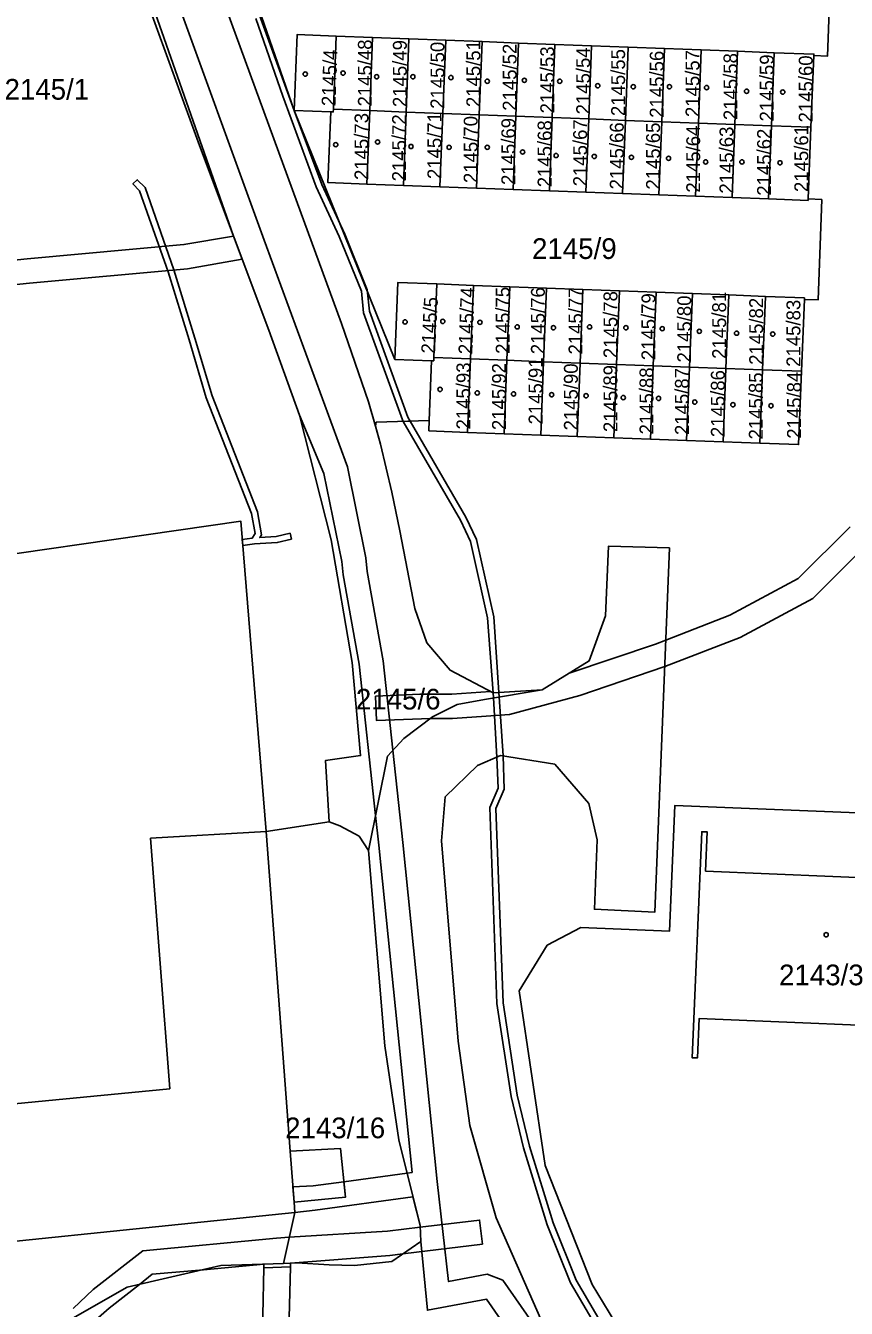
# Model space of a CAD drawing. Extents: x -756746 to -753363, y -1166406 to -1161727.
# Drawn here: x -756523.9 to -756456.5, y -1164106.4 to -1164001 of the extents above; entities that cross this region are included whole.
import ezdxf

# ---------------------------------------------------------------- set-up
doc = ezdxf.new("R2010")
doc.units = 0
for name, color, linetype in [('Hranice parcel', 7, 'Continuous'), ('Parcelní čísla', 7, 'Continuous'), ('Vnitřní kresba', 7, 'Continuous'), ('Věcná břemena k části', 7, 'Continuous'), ('Značky budov', 7, 'Continuous')]:
    doc.layers.add(name, color=color, linetype=linetype)

msp = doc.modelspace()

# ---------------------------------------------------------------- linework, layer by layer
at = {"layer": 'Hranice parcel'}
for p, q in [((-756514.38, -1163973.31), (-756501.8, -1164008)), ((-756498.59, -1164007.9), (-756498.37, -1164001.89)), ((-756498.37, -1164001.89), (-756495.37, -1164002)), ((-756495.6, -1164008.01), (-756495.37, -1164002)), ((-756495.37, -1164002), (-756492.38, -1164002.12)), ((-756492.6, -1164008.13), (-756492.38, -1164002.12)), ((-756492.38, -1164002.12), (-756489.36, -1164002.23)), ((-756489.6, -1164008.24), (-756489.36, -1164002.23)), ((-756489.36, -1164002.23), (-756486.37, -1164002.34)), ((-756486.6, -1164008.35), (-756486.37, -1164002.34)), ((-756486.37, -1164002.34), (-756483.39, -1164002.46)), ((-756483.61, -1164008.47), (-756483.39, -1164002.46)), ((-756483.39, -1164002.46), (-756480.39, -1164002.57)), ((-756480.61, -1164008.58), (-756480.39, -1164002.57)), ((-756480.39, -1164002.57), (-756477.38, -1164002.68)), ((-756477.61, -1164008.69), (-756477.38, -1164002.68)), ((-756477.38, -1164002.68), (-756474.37, -1164002.8)), ((-756474.6, -1164008.81), (-756474.37, -1164002.8)), ((-756474.37, -1164002.8), (-756471.38, -1164002.91)), ((-756471.62, -1164008.92), (-756471.38, -1164002.91)), ((-756471.38, -1164002.91), (-756468.37, -1164003.02)), ((-756468.6, -1164009.03), (-756468.37, -1164003.02)), ((-756468.37, -1164003.02), (-756465.38, -1164003.13)), ((-756465.61, -1164009.14), (-756465.38, -1164003.13)), ((-756465.38, -1164003.13), (-756462.38, -1164003.25)), ((-756462.61, -1164009.26), (-756462.38, -1164003.25)), ((-756459.36, -1164009.38), (-756459.13, -1164003.49)), ((-756501.8, -1164008), (-756498.79, -1164008.11)), ((-756501.8, -1164008), (-756493.54, -1164028.45)), ((-756498.59, -1164007.9), (-756495.6, -1164008.01)), ((-756495.6, -1164008.01), (-756495.83, -1164014.05)), ((-756495.6, -1164008.01), (-756492.6, -1164008.13)), ((-756492.6, -1164008.13), (-756492.83, -1164014.16)), ((-756492.6, -1164008.13), (-756489.6, -1164008.24)), ((-756489.6, -1164008.24), (-756489.84, -1164014.27)), ((-756489.6, -1164008.24), (-756486.6, -1164008.35)), ((-756486.6, -1164008.35), (-756486.83, -1164014.38)), ((-756486.6, -1164008.35), (-756483.61, -1164008.47)), ((-756483.61, -1164008.47), (-756483.83, -1164014.49)), ((-756483.61, -1164008.47), (-756480.61, -1164008.58)), ((-756480.61, -1164008.58), (-756480.84, -1164014.6)), ((-756480.61, -1164008.58), (-756477.61, -1164008.69)), ((-756477.61, -1164008.69), (-756477.85, -1164014.71)), ((-756477.61, -1164008.69), (-756474.6, -1164008.81)), ((-756474.6, -1164008.81), (-756474.83, -1164014.83)), ((-756474.6, -1164008.81), (-756471.62, -1164008.92)), ((-756471.62, -1164008.92), (-756471.86, -1164014.94)), ((-756471.62, -1164008.92), (-756468.6, -1164009.03)), ((-756468.6, -1164009.03), (-756468.84, -1164015.05)), ((-756468.6, -1164009.03), (-756465.61, -1164009.14)), ((-756465.61, -1164009.14), (-756465.84, -1164015.16)), ((-756465.61, -1164009.14), (-756462.61, -1164009.26)), ((-756462.61, -1164009.26), (-756462.84, -1164015.27)), ((-756462.61, -1164009.26), (-756459.36, -1164009.38)), ((-756459.59, -1164015.27), (-756459.36, -1164009.38)), ((-756492.83, -1164014.16), (-756495.83, -1164014.05)), ((-756489.84, -1164014.27), (-756492.83, -1164014.16)), ((-756486.83, -1164014.38), (-756489.84, -1164014.27)), ((-756483.83, -1164014.49), (-756486.83, -1164014.38)), ((-756480.84, -1164014.6), (-756483.83, -1164014.49)), ((-756477.85, -1164014.71), (-756480.84, -1164014.6)), ((-756474.83, -1164014.83), (-756477.85, -1164014.71)), ((-756471.86, -1164014.94), (-756474.83, -1164014.83)), ((-756468.84, -1164015.05), (-756471.86, -1164014.94)), ((-756465.84, -1164015.16), (-756468.84, -1164015.05)), ((-756462.84, -1164015.27), (-756465.84, -1164015.16)), ((-756490.33, -1164028.3), (-756490.08, -1164022.25)), ((-756490.08, -1164022.25), (-756487.07, -1164022.37)), ((-756487.32, -1164028.41), (-756487.07, -1164022.37)), ((-756487.07, -1164022.37), (-756484.09, -1164022.48)), ((-756484.33, -1164028.52), (-756484.09, -1164022.48)), ((-756484.09, -1164022.48), (-756481.09, -1164022.59)), ((-756481.33, -1164028.64), (-756481.09, -1164022.59)), ((-756481.09, -1164022.59), (-756478.09, -1164022.71)), ((-756478.32, -1164028.75), (-756478.09, -1164022.71)), ((-756478.09, -1164022.71), (-756475.08, -1164022.82)), ((-756475.32, -1164028.86), (-756475.08, -1164022.82)), ((-756475.08, -1164022.82), (-756472.07, -1164022.94)), ((-756472.31, -1164028.97), (-756472.07, -1164022.94)), ((-756472.07, -1164022.94), (-756469.09, -1164023.05)), ((-756469.33, -1164029.09), (-756469.09, -1164023.05)), ((-756469.09, -1164023.05), (-756466.1, -1164023.16)), ((-756466.34, -1164029.2), (-756466.1, -1164023.16)), ((-756466.1, -1164023.16), (-756463.09, -1164023.28)), ((-756463.33, -1164029.31), (-756463.09, -1164023.28)), ((-756460.13, -1164029.43), (-756459.9, -1164023.52)), ((-756490.33, -1164028.3), (-756487.32, -1164028.41)), ((-756493.54, -1164028.45), (-756490.54, -1164028.56)), ((-756490.54, -1164028.56), (-756490.73, -1164033.48)), ((-756487.32, -1164028.41), (-756487.56, -1164034.45)), ((-756487.32, -1164028.41), (-756484.33, -1164028.52)), ((-756484.33, -1164028.52), (-756484.56, -1164034.56)), ((-756484.33, -1164028.52), (-756481.33, -1164028.64)), ((-756481.33, -1164028.64), (-756481.56, -1164034.67)), ((-756481.33, -1164028.64), (-756478.32, -1164028.75)), ((-756478.32, -1164028.75), (-756478.55, -1164034.78)), ((-756478.32, -1164028.75), (-756475.32, -1164028.86)), ((-756475.32, -1164028.86), (-756475.55, -1164034.89)), ((-756475.32, -1164028.86), (-756472.31, -1164028.97)), ((-756472.31, -1164028.97), (-756472.55, -1164035)), ((-756472.31, -1164028.97), (-756469.33, -1164029.09)), ((-756469.33, -1164029.09), (-756469.57, -1164035.11)), ((-756469.33, -1164029.09), (-756466.34, -1164029.2)), ((-756466.34, -1164029.2), (-756466.57, -1164035.22)), ((-756466.34, -1164029.2), (-756463.33, -1164029.31)), ((-756463.33, -1164029.31), (-756463.57, -1164035.33)), ((-756463.33, -1164029.31), (-756460.13, -1164029.43)), ((-756490.73, -1164033.48), (-756490.76, -1164034.33)), ((-756490.76, -1164034.33), (-756487.56, -1164034.45)), ((-756487.56, -1164034.45), (-756484.56, -1164034.56)), ((-756484.56, -1164034.56), (-756481.56, -1164034.67)), ((-756481.56, -1164034.67), (-756478.55, -1164034.78)), ((-756478.55, -1164034.78), (-756475.55, -1164034.89)), ((-756475.55, -1164034.89), (-756472.55, -1164035)), ((-756472.55, -1164035), (-756469.57, -1164035.11)), ((-756469.57, -1164035.11), (-756466.57, -1164035.22)), ((-756466.57, -1164035.22), (-756463.57, -1164035.33)), ((-756485.46, -1164055.85), (-756481.45, -1164055.6)), ((-756504.1, -1164067.25), (-756498.94, -1164066.46)), ((-756498.07, -1164066.78), (-756498.94, -1164066.46)), ((-756496.46, -1164067.63), (-756498.07, -1164066.78)), ((-756495.71, -1164068.81), (-756496.46, -1164067.63)), ((-756501.76, -1164098.54), (-756546.2, -1164103.15)), ((-756502.68, -1164102.74), (-756501.76, -1164098.54))]:
    msp.add_line(p, q, dxfattribs=at)
for points in [[(-756495.13, -1164033.93), (-756495.69, -1164031.95), (-756497.93, -1164025.5), (-756501.94, -1164014.53), (-756507.37, -1163999.69), (-756510.62, -1163990.83), (-756512.8, -1163984.85), (-756516.5, -1163974.77), (-756518.28, -1163969.91), (-756519.92, -1163965.45), (-756520.74, -1163963.19), (-756522.25, -1163959.35)], [(-756497.05, -1164053.35), (-756498.78, -1164043.27), (-756501.38, -1164033.04), (-756503.9, -1164026.05), (-756509.58, -1164010.87), (-756513.68, -1163999.59), (-756518.83, -1163985.73), (-756522.65, -1163975.43), (-756522.77, -1163975.11)], [(-756459.13, -1164003.49), (-756458.01, -1164003.54), (-756457.69, -1163995.31), (-756458.82, -1163995.39), (-756458.81, -1163995.27)], [(-756498.37, -1164001.89), (-756501.57, -1164001.77), (-756501.8, -1164008)], [(-756462.38, -1164003.25), (-756459.12, -1164003.37), (-756459.13, -1164003.49)], [(-756495.83, -1164014.05), (-756499.03, -1164013.93), (-756498.79, -1164008.11)], [(-756498.79, -1164008.11), (-756498.6, -1164008.12), (-756498.59, -1164007.9)], [(-756459.59, -1164015.27), (-756459.59, -1164015.39), (-756462.84, -1164015.27)], [(-756459.9, -1164023.52), (-756458.78, -1164023.56), (-756458.47, -1164015.32), (-756459.59, -1164015.27)], [(-756490.08, -1164022.25), (-756493.28, -1164022.13), (-756493.54, -1164028.45)], [(-756463.09, -1164023.28), (-756459.9, -1164023.4), (-756459.9, -1164023.52)], [(-756490.54, -1164028.56), (-756490.34, -1164028.57), (-756490.33, -1164028.3)], [(-756463.57, -1164035.33), (-756460.37, -1164035.45), (-756460.13, -1164029.43)], [(-756490.73, -1164033.48), (-756495.06, -1164033.62), (-756495.13, -1164033.93)], [(-756495.13, -1164033.93), (-756494.71, -1164035.41), (-756493.78, -1164039.37), (-756493.13, -1164042.54), (-756491.91, -1164048.92), (-756490.92, -1164051.75), (-756489, -1164053.99), (-756485.46, -1164055.85)], [(-756504.1, -1164067.25), (-756506.19, -1164041.74), (-756535.05, -1164045.9)], [(-756480.85, -1164108.87), (-756485.22, -1164098.98), (-756487.37, -1164091.4), (-756488.33, -1164084.46), (-756489.72, -1164068), (-756489.4, -1164064.41), (-756486.76, -1164061.81), (-756484.85, -1164061), (-756480.4, -1164061.7), (-756477.61, -1164064.95), (-756476.92, -1164067.93), (-756477.15, -1164073.64), (-756472.17, -1164073.87), (-756470.98, -1164043.94), (-756475.99, -1164043.8), (-756476.23, -1164049.52), (-756477.58, -1164053.23), (-756481.45, -1164055.6)], [(-756498.94, -1164066.46), (-756499.23, -1164061.41), (-756496.36, -1164061.01), (-756497.05, -1164053.35)], [(-756481.45, -1164055.6), (-756486.17, -1164056.39), (-756488.42, -1164056.81), (-756490.44, -1164057.83), (-756492.81, -1164059.6), (-756494.14, -1164061.05), (-756495.71, -1164068.81)], [(-756389.79, -1164078.86), (-756389.34, -1164068.38), (-756470.53, -1164065.1), (-756470.97, -1164075.43), (-756478.27, -1164075.14), (-756481.04, -1164076.59), (-756483.33, -1164080.35), (-756481.19, -1164094.7), (-756477.33, -1164104.46), (-756474.07, -1164109.84), (-756463.94, -1164120.98), (-756462, -1164122.91), (-756448.38, -1164117.4), (-756426.16, -1164129.05), (-756390.59, -1164133.4), (-756390.62, -1164132.03), (-756391.47, -1164122.81), (-756390.01, -1164084.62)], [(-756501.76, -1164098.54), (-756501.82, -1164097.7), (-756497.6, -1164097.3), (-756498, -1164093.3), (-756502.14, -1164093.5), (-756504.1, -1164067.25)], [(-756446.54, -1164068.74), (-756446.52, -1164068.18), (-756446.98, -1164068.16), (-756447.11, -1164071.38), (-756468.02, -1164070.5), (-756467.88, -1164067.28), (-756468.33, -1164067.26), (-756469.13, -1164085.84), (-756468.69, -1164085.85), (-756468.55, -1164082.62), (-756447.59, -1164083.48), (-756447.72, -1164086.71), (-756447.42, -1164086.72)], [(-756495.71, -1164068.81), (-756494.37, -1164084.86), (-756493.21, -1164092.58), (-756491.47, -1164099.62), (-756491.4, -1164100.93), (-756493.8, -1164102.59), (-756496.85, -1164102.91), (-756498.93, -1164102.84), (-756501.58, -1164102.7), (-756502.68, -1164102.74)], [(-756502.68, -1164102.74), (-756507.83, -1164102.92), (-756515.54, -1164104.69), (-756520.36, -1164107.44)]]:
    msp.add_lwpolyline(points, dxfattribs=at)
at = {"layer": 'Vnitřní kresba'}
for p, q in [((-756504.1, -1164067.25), (-756513.6, -1164067.79)), ((-756513.6, -1164067.79), (-756512.02, -1164088.4)), ((-756512.02, -1164088.4), (-756544.05, -1164091.46)), ((-756501.82, -1164097.7), (-756502.14, -1164093.5))]:
    msp.add_line(p, q, dxfattribs=at)
at = {"layer": 'Věcná břemena k části'}
for points in [[(-756476.26, -1164116.2), (-756484.68, -1164104.1), (-756485.95, -1164103.63), (-756489.13, -1164104.23), (-756490.05, -1164096.01), (-756492.88, -1164068.16), (-756493.7, -1164060.57), (-756494.49, -1164053.22), (-756495.81, -1164045.88), (-756495.92, -1164044.77), (-756497.43, -1164037.28), (-756504.27, -1164018.66), (-756512.09, -1163997.16)], [(-756513.97, -1163997.84), (-756506.79, -1164018.32), (-756506.08, -1164020.22), (-756503.9, -1164026.05), (-756501.38, -1164033.04), (-756499.37, -1164037.82), (-756497.9, -1164045.07), (-756497.79, -1164046.16), (-756496.47, -1164053.5), (-756495.13, -1164065.93), (-756494.86, -1164068.36), (-756492.13, -1164095.26), (-756492.53, -1164095.32), (-756497.73, -1164096.03), (-756497.6, -1164097.3), (-756501.82, -1164097.7), (-756501.76, -1164098.54), (-756500.08, -1164098.37), (-756492.05, -1164097.27), (-756491.47, -1164099.62), (-756491.4, -1164100.93), (-756490.87, -1164106.59), (-756486.02, -1164105.67), (-756477.9, -1164117.34)], [(-756504.96, -1164000.43), (-756502.73, -1164006.82), (-756499.99, -1164014.28), (-756498.12, -1164018.35), (-756496.29, -1164022.86), (-756496.11, -1164024.62), (-756492.92, -1164033.43), (-756492.85, -1164033.55), (-756492.27, -1164033.53), (-756492.46, -1164033.21), (-756495.61, -1164024.5), (-756495.81, -1164022.74), (-756497.66, -1164018.15), (-756499.53, -1164014.08), (-756501.8, -1164008), (-756504.48, -1164000.27)], [(-756475.93, -1164108.75), (-756478.64, -1164104.11), (-756480.54, -1164099.4), (-756482.48, -1164093.1), (-756483.48, -1164088.91), (-756484.65, -1164081.33), (-756485.24, -1164065.36), (-756484.55, -1164063.78), (-756484.65, -1164061.03), (-756484.98, -1164056.19), (-756485, -1164055.82), (-756485.42, -1164049.62), (-756486.84, -1164043.25), (-756487.7, -1164041.41), (-756492.27, -1164033.53), (-756492.85, -1164033.55), (-756488.14, -1164041.65), (-756487.32, -1164043.41), (-756485.92, -1164049.7), (-756485.46, -1164055.85), (-756485.44, -1164056.27), (-756485.15, -1164061.13), (-756485.05, -1164063.68), (-756485.74, -1164065.26), (-756485.15, -1164081.37), (-756483.98, -1164089.01), (-756482.96, -1164093.24), (-756481.02, -1164099.56), (-756479.1, -1164104.33), (-756476.35, -1164109.03)], [(-756456.13, -1164042.21), (-756460.4, -1164046.47), (-756466.02, -1164049.48), (-756471.28, -1164051.52), (-756472.13, -1164051.85), (-756479.21, -1164054.23), (-756481.45, -1164055.6), (-756485.46, -1164055.85), (-756485.67, -1164055.74), (-756488.87, -1164055.95), (-756491.48, -1164055.97), (-756495.12, -1164056.13), (-756495.04, -1164058.13), (-756490.62, -1164057.96), (-756488.79, -1164057.95), (-756486.05, -1164057.78), (-756484.13, -1164057.62), (-756478.35, -1164056.07), (-756471.37, -1164053.7), (-756465.18, -1164051.3), (-756459.2, -1164048.09), (-756454.41, -1164043.31)], [(-756486.34, -1164101.15), (-756486.58, -1164099.17), (-756491.46, -1164099.76), (-756494.15, -1164100.09), (-756502.21, -1164100.59), (-756503.26, -1164100.66), (-756514.25, -1164101.69), (-756518.31, -1164104.89), (-756519.97, -1164106.45)], [(-756502.1, -1164102.72), (-756493.95, -1164102.09), (-756492.89, -1164101.96), (-756486.34, -1164101.15)], [(-756520.91, -1164109.84), (-756517.01, -1164106.41), (-756514.52, -1164104.46), (-756513.47, -1164103.63), (-756509.27, -1164103.25), (-756504.29, -1164102.8), (-756504.3, -1164103.1), (-756502.1, -1164103.02), (-756502.1, -1164102.72)]]:
    msp.add_lwpolyline(points, dxfattribs=at)
for points in [[(-756502.03, -1164043.23), (-756502.14, -1164042.74), (-756503.28, -1164043), (-756504.63, -1164043.09), (-756504.5, -1164042.87), (-756504.83, -1164040.97), (-756508.55, -1164031.45), (-756509.96, -1164026.71), (-756511.69, -1164021.1), (-756514.06, -1164014.32), (-756514.7, -1164013.69), (-756515.05, -1164014.04), (-756514.5, -1164014.6), (-756512.17, -1164021.26), (-756510.44, -1164026.85), (-756509.03, -1164031.61), (-756505.31, -1164041.11), (-756505.02, -1164042.77), (-756505.25, -1164043.14), (-756506.07, -1164043.24), (-756506.03, -1164043.74), (-756505.08, -1164043.62), (-756503.2, -1164043.5)], [(-756558.8, -1164023.25), (-756558.74, -1164027.43), (-756556.75, -1164027.33), (-756556.78, -1164025.11), (-756547.68, -1164024.41), (-756546.14, -1164024.21), (-756541.69, -1164024.06), (-756523.54, -1164022.18), (-756510.58, -1164021), (-756506.08, -1164020.22), (-756506.79, -1164018.32), (-756510.86, -1164019.02), (-756523.74, -1164020.18), (-756541.83, -1164022.06), (-756546.3, -1164022.21), (-756547.88, -1164022.43)], [(-756500.26, -1164096.37), (-756501.92, -1164096.45), (-756501.82, -1164097.7), (-756497.6, -1164097.3), (-756497.73, -1164096.03)], [(-756501.99, -1164115.02), (-756502.21, -1164107.2), (-756502.1, -1164103.02), (-756504.3, -1164103.1), (-756504.38, -1164106.98), (-756504.2, -1164114.94)]]:
    msp.add_lwpolyline(points, close=True, dxfattribs=at)
at = {"layer": 'Značky budov'}
for centre in [(-756500.9, -1164005.01), (-756497.79, -1164004.93), (-756495.03, -1164005.23), (-756492.06, -1164005.23), (-756488.93, -1164005.3), (-756485.95, -1164005.6), (-756482.9, -1164005.52), (-756479.99, -1164005.6), (-756476.87, -1164005.97), (-756473.96, -1164006.05), (-756470.98, -1164006.05), (-756467.93, -1164006.12), (-756464.65, -1164006.42), (-756461.68, -1164006.49), (-756494.96, -1164010.59), (-756498.39, -1164010.81), (-756492.21, -1164010.96), (-756489.08, -1164011.03), (-756485.95, -1164011.03), (-756483.05, -1164011.41), (-756480.29, -1164011.7), (-756477.16, -1164011.78), (-756474.11, -1164011.85), (-756471.06, -1164011.93), (-756468.01, -1164012.23), (-756465.03, -1164012.23), (-756461.9, -1164012.3), (-756492.7, -1164025.37), (-756489.6, -1164025.33), (-756486.55, -1164025.41), (-756483.49, -1164025.78), (-756480.51, -1164025.85), (-756477.54, -1164025.78), (-756474.56, -1164025.85), (-756471.58, -1164025.93), (-756468.53, -1164026.15), (-756465.47, -1164026.3), (-756462.5, -1164026.37), (-756489.82, -1164030.92), (-756486.77, -1164031.21), (-756483.79, -1164031.29), (-756480.66, -1164031.36), (-756477.83, -1164031.44), (-756474.78, -1164031.59), (-756471.88, -1164031.66), (-756468.9, -1164031.96), (-756465.77, -1164032.18), (-756462.64, -1164032.26), (-756458.11, -1164075.73)]:
    msp.add_circle(centre, 0.175, dxfattribs=at)

# ---------------------------------------------------------------- texts
at = {"layer": 'Parcelní čísla'}
for s, rotation, p in [('2145/4', 88, (-756498.42, -1164007.67)), ('2145/48', 90, (-756495.43, -1164007.67)), ('2145/49', 90, (-756492.56, -1164007.72)), ('2145/50', 90, (-756489.47, -1164007.86)), ('2145/51', 90, (-756486.52, -1164007.72)), ('2145/52', 90, (-756483.54, -1164008.02)), ('2145/53', 90, (-756480.45, -1164008.24)), ('2145/54', 90, (-756477.5, -1164008.32)), ('2145/55', 90, (-756474.63, -1164008.46)), ('2145/56', 90, (-756471.46, -1164008.6)), ('2145/57', 90, (-756468.52, -1164008.54)), ('2145/58', 90, (-756465.4, -1164008.79)), ('2145/59', 90, (-756462.42, -1164008.9)), ('2145/60', 90, (-756459.22, -1164008.98)), ('2145/73', 90, (-756495.71, -1164013.71)), ('2145/71', 90, (-756489.72, -1164013.63)), ('2145/72', 90, (-756492.62, -1164013.82)), ('2145/70', 90, (-756486.74, -1164013.96)), ('2145/69', 90, (-756483.65, -1164014.12)), ('2145/68', 90, (-756480.67, -1164014.31)), ('2145/67', 90, (-756477.75, -1164014.23)), ('2145/66', 90, (-756474.74, -1164014.48)), ('2145/65', 90, (-756471.76, -1164014.5)), ('2145/64', 90, (-756468.46, -1164014.75)), ('2145/63', 90, (-756465.73, -1164014.83)), ('2145/61', 90, (-756459.58, -1164014.7)), ('2145/62', 90, (-756462.64, -1164015)), ('2145/74', 88, (-756487.18, -1164028.05)), ('2145/75', 90, (-756484.11, -1164028)), ('2145/76', 90, (-756481.22, -1164028.03)), ('2145/77', 90, (-756478.13, -1164028.05)), ('2145/78', 90, (-756475.26, -1164028.35)), ('2145/79', 90, (-756472.14, -1164028.52)), ('2145/81', 90, (-756466.33, -1164028.41)), ('2145/5', 87, (-756490.24, -1164028.01)), ('2145/80', 90, (-756469.2, -1164028.71)), ('2145/82', 90, (-756463.29, -1164028.9)), ('2145/83', 90, (-756460.23, -1164029.06)), ('2145/91', 90, (-756481.41, -1164033.8)), ('2145/93', 90, (-756487.34, -1164034.21)), ('2145/92', 90, (-756484.41, -1164034.26)), ('2145/90', 90, (-756478.51, -1164034.29)), ('2145/89', 90, (-756475.26, -1164034.42)), ('2145/88', 90, (-756472.3, -1164034.62)), ('2145/87', 90, (-756469.39, -1164034.67)), ('2145/86', 90, (-756466.44, -1164034.84)), ('2145/85', 90, (-756463.32, -1164035.03)), ('2145/84', 90, (-756460.18, -1164034.97))]:
    msp.add_text(s, height=1.139, rotation=rotation, dxfattribs=at).set_placement(p)
for s, p in [('2145/1', (-756525.6, -1164007.11)), ('2145/9', (-756482.27, -1164020.2)), ('2145/6', (-756496.74, -1164057.22)), ('2143/3', (-756461.98, -1164079.88)), ('2143/16', (-756502.55, -1164092.45))]:
    msp.add_text(s, height=1.7, dxfattribs=at).set_placement(p)

doc.saveas('drawing.dxf')
